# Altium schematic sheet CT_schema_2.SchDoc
size 276 x 169 mm
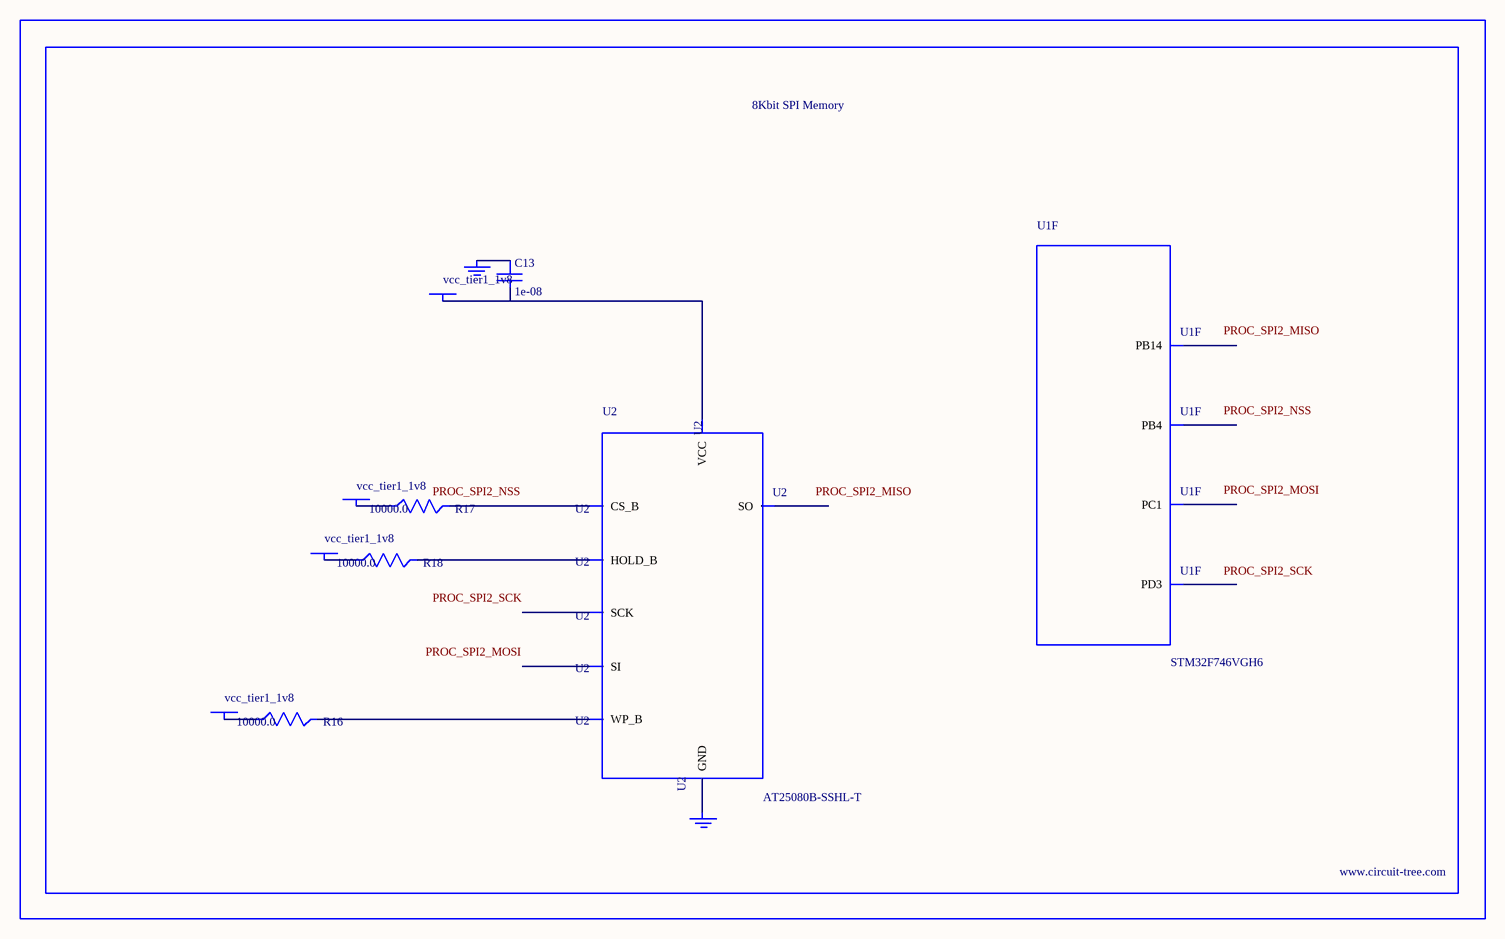
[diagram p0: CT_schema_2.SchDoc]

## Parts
BORDER1  (no value)
C13  1e-08  [C0402]
GND_INSTANCE_1_0  (no value)
GND_INSTANCE_1_1  (no value)
POWER_INSTANCE_1_0  vcc_tier1_1v8
POWER_INSTANCE_1_1  vcc_tier1_1v8
POWER_INSTANCE_1_2  vcc_tier1_1v8
POWER_INSTANCE_1_3  vcc_tier1_1v8
R16  10000.0  [R0603]
R17  10000.0  [R0603]
R18  10000.0  [R0603]
U1  STM32F746VGH6  [TFBGA100]  (part F of 10)
U2  AT25080B-SSHL-T  [SOIC-8]

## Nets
NetC13_1: C13.1 GND_INSTANCE_1_0.0(GND)
NetC13_2: C13.2 POWER_INSTANCE_1_3.0(PWR) U2.8(VCC)
NetGND_INSTANCE_1_1_0: GND_INSTANCE_1_1.0(GND) U2.4(GND)
NetPOWER_INSTANCE_1_0_0: POWER_INSTANCE_1_0.0(PWR) R17.1
NetPOWER_INSTANCE_1_1_0: POWER_INSTANCE_1_1.0(PWR) R16.1
NetPOWER_INSTANCE_1_2_0: POWER_INSTANCE_1_2.0(PWR) R18.1
NetR16_2: R16.2 U2.3(WP_B)
NetR17_2: R17.2 U2.1(CS_B)
NetR18_2: R18.2 U2.7(HOLD_B)

Not connected (* = marked no-connect by the designer): U1 A6(PB4) C7(PD3) F2(PC1) H10(PB14); U2 2(SO) 5(SI) 6(SCK)

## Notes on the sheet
- Labels drawn without touching a wire or pin: PROC_SPI2_MISO, PROC_SPI2_MOSI, PROC_SPI2_NSS, PROC_SPI2_SCK

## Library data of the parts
BORDER1 = BORDER_PAGE1
C13 = C0402C103K3RAC
GND_INSTANCE_1_0 GND_INSTANCE_1_1 = GND
POWER_INSTANCE_1_0-POWER_INSTANCE_1_3 = PWR
R16-R18 = RC0603JR-0710KL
